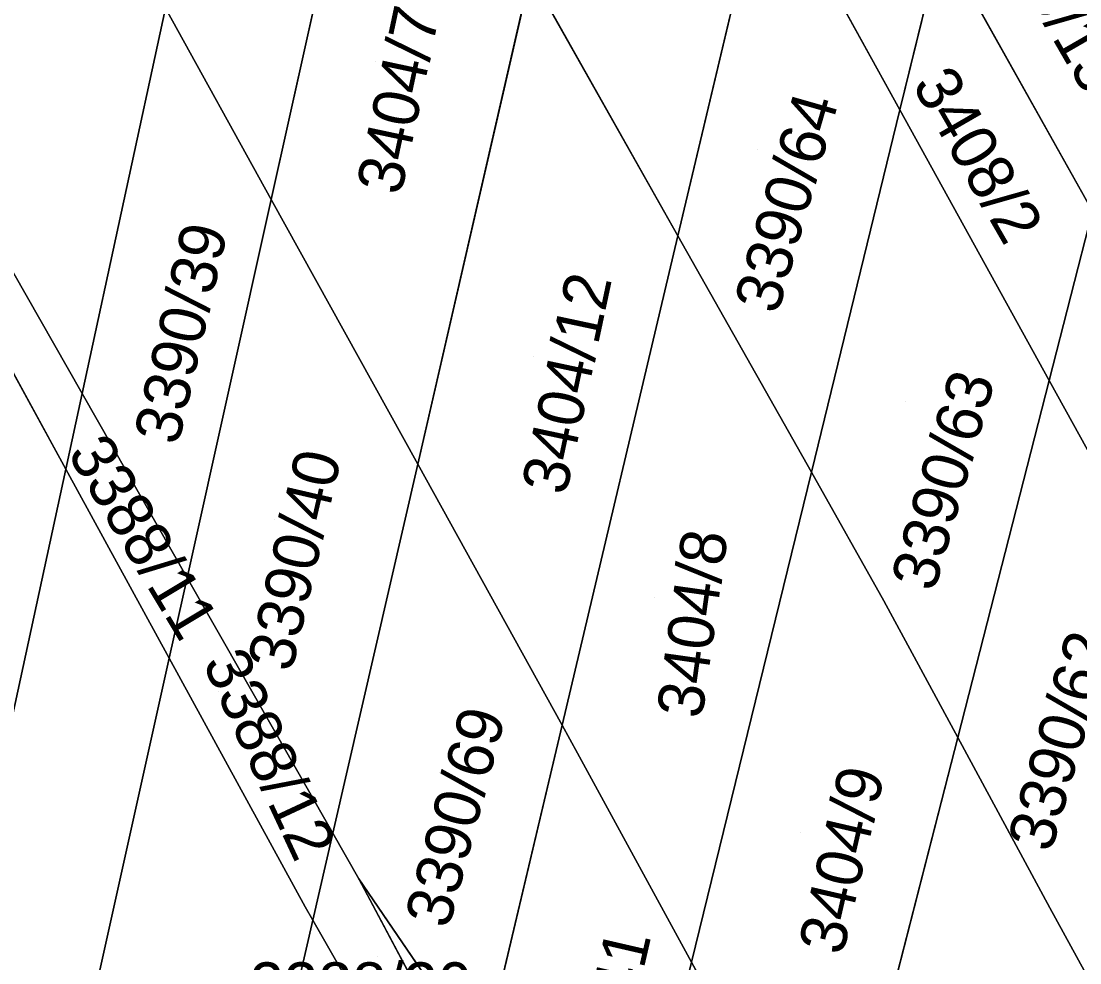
# Model space of a CAD drawing. Extents: x -262715 to -259381, y -1237238 to -1231182.
# Drawn here: x -261850.05 to -261803.95, y -1236094.55 to -1236053.56 of the extents above; entities that cross this region are included whole.
import ezdxf

# ---------------------------------------------------------------- set-up
doc = ezdxf.new("R2010")
doc.units = 0
for name, color, linetype in [('body_kn', 7, 'Continuous'), ('kladpar_druhypozemkov', 7, 'Continuous'), ('kladpar_hranice', 7, 'Continuous'), ('kladpar_parcelnecisla', 7, 'Continuous'), ('kladpar_plochy', 7, 'Continuous')]:
    doc.layers.add(name, color=color, linetype=linetype)

msp = doc.modelspace()

# ---------------------------------------------------------------- linework, layer by layer
at = {"layer": 'body_kn'}
for p, q in [((-261811.79, -1236057.43), (-261811.79, -1236057.43)), ((-261839.16, -1236061.32), (-261839.16, -1236061.32)), ((-261839.16, -1236061.32), (-261839.16, -1236061.32)), ((-261821.45, -1236062.91), (-261821.45, -1236062.91)), ((-261805.29, -1236069.2), (-261805.29, -1236069.2)), ((-261847.4, -1236069.77), (-261847.4, -1236069.77)), ((-261847.4, -1236069.77), (-261847.4, -1236069.77)), ((-261832.78, -1236072.84), (-261832.78, -1236072.84)), ((-261832.78, -1236072.84), (-261832.78, -1236072.84)), ((-261848.11, -1236073.06), (-261848.11, -1236073.06)), ((-261848.11, -1236073.06), (-261848.11, -1236073.06)), ((-261815.64, -1236073.19), (-261815.64, -1236073.19)), ((-261815.64, -1236073.19), (-261815.64, -1236073.19)), ((-261842.82, -1236077.79), (-261842.82, -1236077.79)), ((-261812.48, -1236078.8), (-261812.48, -1236078.8)), ((-261843.6, -1236081.29), (-261843.6, -1236081.29)), ((-261843.6, -1236081.29), (-261843.6, -1236081.29)), ((-261826.49, -1236084.21), (-261826.49, -1236084.21)), ((-261826.49, -1236084.21), (-261826.49, -1236084.21)), ((-261809.27, -1236084.74), (-261809.27, -1236084.74)), ((-261809.27, -1236084.74), (-261809.27, -1236084.74)), ((-261825.82, -1236085.42), (-261825.82, -1236085.42)), ((-261825.82, -1236085.42), (-261825.82, -1236085.42)), ((-261836.48, -1236088.91), (-261836.48, -1236088.91)), ((-261836.48, -1236088.91), (-261836.48, -1236088.91)), ((-261835.35, -1236090.89), (-261835.35, -1236090.89)), ((-261835.35, -1236090.89), (-261835.35, -1236090.89)), ((-261837.68, -1236092.11), (-261837.68, -1236092.11)), ((-261805.26, -1236092.16), (-261805.26, -1236092.16)), ((-261837.35, -1236092.69), (-261837.35, -1236092.69)), ((-261837.35, -1236092.69), (-261837.35, -1236092.69)), ((-261820.86, -1236094.52), (-261820.86, -1236094.52)), ((-261820.86, -1236094.52), (-261820.86, -1236094.52))]:
    msp.add_line(p, q, dxfattribs=at)
at = {"layer": 'kladpar_druhypozemkov'}
for p, q in [((-261834.63, -1236055.32), (-261834.63, -1236055.32)), ((-261807.69, -1236058.53), (-261807.69, -1236058.53)), ((-261817.98, -1236059.16), (-261817.98, -1236059.16)), ((-261843.92, -1236066.4), (-261843.92, -1236066.4)), ((-261827.74, -1236068.16), (-261827.74, -1236068.16)), ((-261811.54, -1236070.1), (-261811.54, -1236070.1)), ((-261846.78, -1236073.43), (-261846.78, -1236073.43)), ((-261839.03, -1236075.27), (-261839.03, -1236075.27)), ((-261822.46, -1236078.66), (-261822.46, -1236078.66)), ((-261841.44, -1236082.75), (-261841.44, -1236082.75)), ((-261805.24, -1236082.9), (-261805.24, -1236082.9)), ((-261831.85, -1236086.26), (-261831.85, -1236086.26)), ((-261816.1, -1236088.89), (-261816.1, -1236088.89)), ((-261834.53, -1236094.27), (-261834.53, -1236094.27))]:
    msp.add_line(p, q, dxfattribs=at)
at = {"layer": 'kladpar_hranice'}
for p, q in [((-261834.4, -1236039.94), (-261839.16, -1236061.32)), ((-261839.16, -1236061.32), (-261834.4, -1236039.94)), ((-261821.45, -1236062.91), (-261817.64, -1236046.83)), ((-261817.64, -1236046.83), (-261821.45, -1236062.91)), ((-261817.64, -1236046.83), (-261811.79, -1236057.43)), ((-261811.79, -1236057.43), (-261817.64, -1236046.83)), ((-261811.79, -1236057.43), (-261809.99, -1236050.08)), ((-261809.99, -1236050.08), (-261811.79, -1236057.43)), ((-261809.99, -1236050.08), (-261803.4, -1236061.83)), ((-261803.4, -1236061.83), (-261809.99, -1236050.08)), ((-261832.78, -1236072.84), (-261827.88, -1236051.52)), ((-261827.88, -1236051.52), (-261832.78, -1236072.84)), ((-261827.88, -1236051.52), (-261821.45, -1236062.91)), ((-261821.45, -1236062.91), (-261827.88, -1236051.52)), ((-261847.4, -1236069.77), (-261843.77, -1236053)), ((-261843.77, -1236053), (-261847.4, -1236069.77)), ((-261843.77, -1236053), (-261839.16, -1236061.32)), ((-261839.16, -1236061.32), (-261843.77, -1236053)), ((-261815.64, -1236073.19), (-261811.79, -1236057.43)), ((-261811.79, -1236057.43), (-261815.64, -1236073.19)), ((-261811.79, -1236057.43), (-261805.29, -1236069.2)), ((-261805.29, -1236069.2), (-261811.79, -1236057.43)), ((-261839.16, -1236061.32), (-261842.82, -1236077.79)), ((-261842.82, -1236077.79), (-261839.16, -1236061.32)), ((-261832.78, -1236072.84), (-261839.16, -1236061.32)), ((-261839.16, -1236061.32), (-261832.78, -1236072.84)), ((-261803.4, -1236061.83), (-261805.29, -1236069.2)), ((-261805.29, -1236069.2), (-261803.4, -1236061.83)), ((-261826.49, -1236084.21), (-261821.45, -1236062.91)), ((-261821.45, -1236062.91), (-261826.49, -1236084.21)), ((-261815.64, -1236073.19), (-261821.45, -1236062.91)), ((-261821.45, -1236062.91), (-261815.64, -1236073.19)), ((-261848.11, -1236073.06), (-261852.61, -1236064.84)), ((-261809.27, -1236084.74), (-261805.29, -1236069.2)), ((-261805.29, -1236069.2), (-261809.27, -1236084.74)), ((-261847.4, -1236069.77), (-261848.11, -1236073.06)), ((-261847.4, -1236069.77), (-261842.82, -1236077.79)), ((-261842.82, -1236077.79), (-261847.4, -1236069.77)), ((-261836.48, -1236088.91), (-261832.78, -1236072.84)), ((-261832.78, -1236072.84), (-261836.48, -1236088.91)), ((-261826.49, -1236084.21), (-261832.78, -1236072.84)), ((-261832.78, -1236072.84), (-261826.49, -1236084.21)), ((-261848.11, -1236073.06), (-261843.6, -1236081.29)), ((-261815.64, -1236073.19), (-261820.86, -1236094.52)), ((-261820.86, -1236094.52), (-261815.64, -1236073.19)), ((-261842.82, -1236077.79), (-261843.6, -1236081.29)), ((-261836.48, -1236088.91), (-261842.82, -1236077.79)), ((-261842.82, -1236077.79), (-261836.48, -1236088.91)), ((-261829.95, -1236098.8), (-261826.49, -1236084.21)), ((-261826.49, -1236084.21), (-261829.95, -1236098.8)), ((-261825.82, -1236085.42), (-261826.49, -1236084.21)), ((-261809.27, -1236084.74), (-261814.68, -1236105.86)), ((-261814.68, -1236105.86), (-261809.27, -1236084.74)), ((-261820.86, -1236094.52), (-261825.82, -1236085.42)), ((-261836.48, -1236088.91), (-261837.35, -1236092.69)), ((-261835.35, -1236090.89), (-261836.48, -1236088.91)), ((-261835.35, -1236090.89), (-261829.95, -1236098.8)), ((-261830.31, -1236100.35), (-261835.35, -1236090.89)), ((-261829.95, -1236098.8), (-261835.35, -1236090.89)), ((-261820.86, -1236094.52), (-261824.03, -1236107.47)), ((-261824.03, -1236107.47), (-261820.86, -1236094.52)), ((-261820.86, -1236094.52), (-261814.68, -1236105.86)), ((-261814.68, -1236105.86), (-261820.86, -1236094.52))]:
    msp.add_line(p, q, dxfattribs=at)
for points in [[(-261856.36, -1236054.03), (-261855.26, -1236055.99), (-261847.4, -1236069.77)], [(-261847.4, -1236069.77), (-261855.26, -1236055.99), (-261856.36, -1236054.03)], [(-261852.61, -1236064.84), (-261848.11, -1236073.06), (-261896.9, -1236298.59)], [(-261805.29, -1236069.2), (-261802.94, -1236073.45), (-261799.63, -1236081.18)], [(-261799.63, -1236081.18), (-261802.94, -1236073.45), (-261805.29, -1236069.2)], [(-261843.6, -1236081.29), (-261848.11, -1236073.06), (-261847.4, -1236069.77)], [(-261843.6, -1236081.29), (-261892.67, -1236301.85), (-261896.9, -1236298.59), (-261848.11, -1236073.06)], [(-261809.27, -1236084.74), (-261812.48, -1236078.8), (-261815.64, -1236073.19)], [(-261815.64, -1236073.19), (-261812.48, -1236078.8), (-261809.27, -1236084.74)], [(-261837.35, -1236092.69), (-261837.68, -1236092.11), (-261843.6, -1236081.29), (-261842.82, -1236077.79)], [(-261837.35, -1236092.69), (-261886.52, -1236306.43), (-261892.67, -1236301.85), (-261843.6, -1236081.29)], [(-261843.6, -1236081.29), (-261837.68, -1236092.11), (-261837.35, -1236092.69)], [(-261826.49, -1236084.21), (-261825.82, -1236085.42), (-261820.86, -1236094.52)], [(-261803.43, -1236095.49), (-261805.26, -1236092.16), (-261809.27, -1236084.74)], [(-261809.27, -1236084.74), (-261805.26, -1236092.16), (-261803.43, -1236095.49)], [(-261831.09, -1236103.63), (-261837.35, -1236092.69), (-261836.48, -1236088.91)], [(-261836.48, -1236088.91), (-261835.35, -1236090.89), (-261830.31, -1236100.35)], [(-261886.52, -1236306.43), (-261837.35, -1236092.69), (-261831.09, -1236103.63), (-261880.24, -1236311.16)]]:
    msp.add_lwpolyline(points, dxfattribs=at)
at = {"layer": 'kladpar_plochy'}
for points in [[(-261839.16, -1236061.32), (-261843.77, -1236053), (-261839.1, -1236031.45), (-261834.4, -1236039.94)], [(-261824.24, -1236035.73), (-261822.42, -1236038.17), (-261817.64, -1236046.83), (-261821.45, -1236062.91), (-261827.88, -1236051.52)], [(-261852.75, -1236036.84), (-261847.06, -1236047.05), (-261843.77, -1236053), (-261847.4, -1236069.77), (-261855.26, -1236055.99), (-261856.36, -1236054.03), (-261856.27, -1236053.61)], [(-261815.91, -1236039.53), (-261809.99, -1236050.08), (-261811.79, -1236057.43), (-261817.64, -1236046.83)], [(-261832.78, -1236072.84), (-261839.16, -1236061.32), (-261834.4, -1236039.94), (-261833.76, -1236041.1), (-261827.88, -1236051.52)], [(-261803.4, -1236061.83), (-261809.99, -1236050.08), (-261807.78, -1236041.07), (-261801.15, -1236053.06)], [(-261815.64, -1236073.19), (-261821.45, -1236062.91), (-261817.64, -1236046.83), (-261811.79, -1236057.43)], [(-261809.99, -1236050.08), (-261803.4, -1236061.83), (-261805.29, -1236069.2), (-261811.79, -1236057.43)], [(-261826.49, -1236084.21), (-261832.78, -1236072.84), (-261827.88, -1236051.52), (-261821.45, -1236062.91)], [(-261843.77, -1236053), (-261839.16, -1236061.32), (-261842.82, -1236077.79), (-261847.4, -1236069.77)], [(-261852.61, -1236064.84), (-261856.96, -1236056.91), (-261856.36, -1236054.03), (-261855.26, -1236055.99), (-261847.4, -1236069.77), (-261848.11, -1236073.06)], [(-261809.27, -1236084.74), (-261812.48, -1236078.8), (-261815.64, -1236073.19), (-261811.79, -1236057.43), (-261805.29, -1236069.2)], [(-261836.48, -1236088.91), (-261842.82, -1236077.79), (-261839.16, -1236061.32), (-261832.78, -1236072.84)], [(-261803.4, -1236061.83), (-261798.5, -1236070.56), (-261797.35, -1236072.6), (-261799.63, -1236081.18), (-261802.94, -1236073.45), (-261805.29, -1236069.2)], [(-261825.82, -1236085.42), (-261826.49, -1236084.21), (-261821.45, -1236062.91), (-261815.64, -1236073.19), (-261820.86, -1236094.52)], [(-261901.85, -1236294.78), (-261852.61, -1236064.84), (-261848.11, -1236073.06), (-261896.9, -1236298.59)], [(-261803.43, -1236095.49), (-261805.26, -1236092.16), (-261809.27, -1236084.74), (-261805.29, -1236069.2), (-261802.94, -1236073.45), (-261799.63, -1236081.18)], [(-261847.4, -1236069.77), (-261842.82, -1236077.79), (-261843.6, -1236081.29), (-261848.11, -1236073.06)], [(-261835.35, -1236090.89), (-261836.48, -1236088.91), (-261832.78, -1236072.84), (-261826.49, -1236084.21), (-261829.95, -1236098.8)], [(-261843.6, -1236081.29), (-261892.67, -1236301.85), (-261896.9, -1236298.59), (-261848.11, -1236073.06)], [(-261814.68, -1236105.86), (-261820.86, -1236094.52), (-261815.64, -1236073.19), (-261812.48, -1236078.8), (-261809.27, -1236084.74)], [(-261837.35, -1236092.69), (-261837.68, -1236092.11), (-261843.6, -1236081.29), (-261842.82, -1236077.79), (-261836.48, -1236088.91)], [(-261843.6, -1236081.29), (-261837.68, -1236092.11), (-261837.35, -1236092.69), (-261886.52, -1236306.43), (-261892.67, -1236301.85)], [(-261826.49, -1236084.21), (-261825.82, -1236085.42), (-261820.86, -1236094.52), (-261824.03, -1236107.47), (-261829.95, -1236098.8)], [(-261810.55, -1236113.44), (-261814.68, -1236105.86), (-261809.27, -1236084.74), (-261805.26, -1236092.16), (-261803.43, -1236095.49), (-261807.84, -1236112.12)], [(-261831.09, -1236103.63), (-261837.35, -1236092.69), (-261836.48, -1236088.91), (-261835.35, -1236090.89), (-261830.31, -1236100.35)], [(-261835.35, -1236090.89), (-261829.95, -1236098.8), (-261830.31, -1236100.35)], [(-261886.52, -1236306.43), (-261837.35, -1236092.69), (-261831.09, -1236103.63), (-261880.24, -1236311.16)], [(-261820.86, -1236094.52), (-261814.68, -1236105.86), (-261817.54, -1236117.02), (-261817.75, -1236116.68), (-261824.03, -1236107.47)]]:
    msp.add_lwpolyline(points, close=True, dxfattribs=at)

# ---------------------------------------------------------------- texts
at = {"layer": 'kladpar_parcelnecisla'}
for s, rotation, p in [('3410/13', 300, (-261808.535, -1236048.482)), ('3404/7', 78, (-261833.518, -1236061.187)), ('3408/2', 300, (-261811.287, -1236056.332)), ('3390/64', 74, (-261817.114, -1236066.374)), ('3390/39', 77, (-261843.215, -1236072.071)), ('3404/12', 78, (-261826.33, -1236074.25)), ('3390/63', 74, (-261810.292, -1236078.453)), ('3388/11', 301, (-261848.069, -1236072.375)), ('3390/40', 77, (-261838.269, -1236081.942)), ('3404/8', 82, (-261820.407, -1236083.968)), ('3390/62', 74, (-261805.208, -1236089.798)), ('3388/12', 295, (-261842.175, -1236081.492)), ('3390/69', 75, (-261831.44, -1236093.115)), ('3404/9', 77, (-261814.277, -1236094.271)), ('3390/41', 77, (-261824.79, -1236102.832))]:
    msp.add_text(s, height=2, rotation=rotation, dxfattribs=at).set_placement(p)
msp.add_text('3388/30', height=2, dxfattribs=at).set_placement((-261840.092, -1236096.53))

doc.saveas('drawing.dxf')
